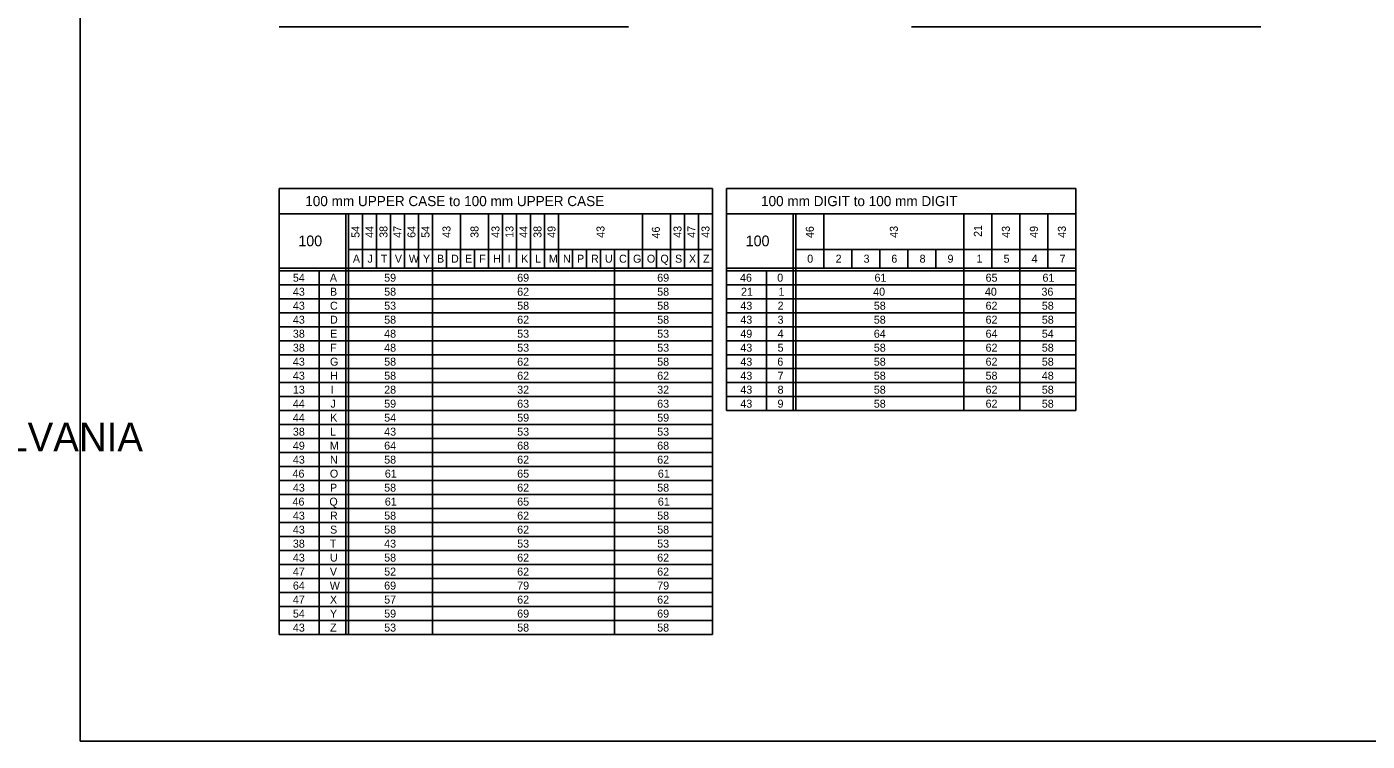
# Model space of a CAD drawing. Extents: x 637580 to 641849, y 297270 to 299646.
# Drawn here: x 638441 to 638944, y 297879 to 298147 of the extents above; entities that cross this region are included whole.
import ezdxf

# ---------------------------------------------------------------- set-up
doc = ezdxf.new("R2010")
doc.units = 0
doc.layers.add('1', color=7, linetype='Continuous')
doc.layers.add('2', color=7, linetype='Continuous')

msp = doc.modelspace()

# ---------------------------------------------------------------- linework, layer by layer
at = {"layer": '1'}
for p, q in [((638461.31, 298442.63), (638461.31, 297878.63)), ((639247.31, 297878.63), (638461.31, 297878.63)), ((638461.31, 297878.63), (639047.31, 297878.63))]:
    msp.add_line(p, q, dxfattribs=at)
at = {"layer": '2'}
for p, q in [((638535.94, 298146.63), (638666.94, 298146.63)), ((638773.06, 298146.63), (638904.06, 298146.63)), ((638698.44, 298086), (638535.94, 298086)), ((638535.94, 298086), (638535.94, 297918.63)), ((638698.44, 298086), (638698.44, 297918.63)), ((638834.69, 298086), (638703.69, 298086)), ((638703.69, 298086), (638703.69, 298002.63)), ((638834.69, 298002.63), (638834.69, 298086)), ((638535.94, 298076.5), (638698.44, 298076.5)), ((638560.94, 298076.5), (638560.94, 297918.63)), ((638561.94, 298076.5), (638561.94, 297918.63)), ((638567.19, 298076.5), (638567.19, 298056.13)), ((638572.44, 298076.5), (638572.44, 298056.13)), ((638577.69, 298076.5), (638577.69, 298056.13)), ((638582.94, 298076.5), (638582.94, 298056.13)), ((638588.19, 298076.5), (638588.19, 298056.13)), ((638593.44, 298076.5), (638593.44, 297918.63)), ((638603.94, 298076.5), (638603.94, 298056.13)), ((638614.44, 298076.5), (638614.44, 298056.13)), ((638619.69, 298076.5), (638619.69, 298056.13)), ((638624.94, 298076.5), (638624.94, 298056.13)), ((638630.19, 298076.5), (638630.19, 298056.13)), ((638635.44, 298076.5), (638635.44, 298056.13)), ((638640.69, 298076.5), (638640.69, 298056.13)), ((638672.19, 298076.5), (638672.19, 298056.13)), ((638682.69, 298076.5), (638682.69, 298056.13)), ((638687.94, 298076.5), (638687.94, 298056.13)), ((638693.19, 298076.5), (638693.19, 298056.13)), ((638703.69, 298076.5), (638834.69, 298076.5)), ((638728.69, 298076.5), (638728.69, 298002.63)), ((638729.69, 298076.5), (638729.69, 298002.63)), ((638740.19, 298076.5), (638740.19, 298056.13)), ((638792.69, 298076.5), (638792.69, 298002.63)), ((638803.19, 298076.5), (638803.19, 298056.13)), ((638813.69, 298076.5), (638813.69, 298002.63)), ((638824.19, 298076.5), (638824.19, 298056.13)), ((638561.94, 298063.13), (638698.44, 298063.13)), ((638598.69, 298063.13), (638598.69, 298056.13)), ((638609.19, 298063.13), (638609.19, 298056.13)), ((638645.94, 298063.13), (638645.94, 298056.13)), ((638651.19, 298063.13), (638651.19, 298056.13)), ((638656.44, 298063.13), (638656.44, 298056.13)), ((638656.44, 298063.13), (638656.44, 298056.13)), ((638661.69, 298063.13), (638661.69, 297918.63)), ((638666.94, 298063.13), (638666.94, 298056.13)), ((638677.44, 298063.13), (638677.44, 298056.13)), ((638729.69, 298063.13), (638834.69, 298063.13)), ((638750.69, 298063.13), (638750.69, 298056.13)), ((638761.19, 298063.13), (638761.19, 298056.13)), ((638771.69, 298063.13), (638771.69, 298056.13)), ((638782.19, 298063.13), (638782.19, 298056.13)), ((638698.44, 298056.13), (638535.94, 298056.13)), ((638698.44, 298055.13), (638535.94, 298055.13)), ((638550.94, 298055.13), (638550.94, 297918.63)), ((638834.69, 298056.13), (638703.69, 298056.13)), ((638834.69, 298055.13), (638703.69, 298055.13)), ((638718.69, 298055.13), (638718.69, 298002.63)), ((638698.44, 298049.88), (638535.94, 298049.88)), ((638834.69, 298049.88), (638703.69, 298049.88)), ((638698.44, 298044.63), (638535.94, 298044.63)), ((638834.69, 298044.63), (638703.69, 298044.63)), ((638698.44, 298039.38), (638535.94, 298039.38)), ((638834.69, 298039.38), (638703.69, 298039.38)), ((638698.44, 298034.13), (638535.94, 298034.13)), ((638834.69, 298034.13), (638703.69, 298034.13)), ((638698.44, 298028.88), (638535.94, 298028.88)), ((638834.69, 298028.88), (638703.69, 298028.88)), ((638698.44, 298023.63), (638535.94, 298023.63)), ((638834.69, 298023.63), (638703.69, 298023.63)), ((638698.44, 298018.38), (638535.94, 298018.38)), ((638834.69, 298018.38), (638703.69, 298018.38)), ((638698.44, 298013.13), (638535.94, 298013.13)), ((638834.69, 298013.13), (638703.69, 298013.13)), ((638698.44, 298007.88), (638535.94, 298007.88)), ((638834.69, 298007.88), (638703.69, 298007.88)), ((638698.44, 298002.63), (638535.94, 298002.63)), ((638703.69, 298002.63), (638834.69, 298002.63)), ((638698.44, 297997.38), (638535.94, 297997.38)), ((638698.44, 297992.13), (638535.94, 297992.13)), ((638698.44, 297986.88), (638535.94, 297986.88)), ((638698.44, 297981.63), (638535.94, 297981.63)), ((638698.44, 297976.38), (638535.94, 297976.38)), ((638698.44, 297971.13), (638535.94, 297971.13)), ((638698.44, 297965.88), (638535.94, 297965.88)), ((638698.44, 297960.63), (638535.94, 297960.63)), ((638698.44, 297955.38), (638535.94, 297955.38)), ((638698.44, 297950.13), (638535.94, 297950.13)), ((638698.44, 297944.88), (638535.94, 297944.88)), ((638698.44, 297939.63), (638535.94, 297939.63)), ((638698.44, 297934.38), (638535.94, 297934.38)), ((638698.44, 297929.13), (638535.94, 297929.13)), ((638698.44, 297923.88), (638535.94, 297923.88)), ((638535.94, 297918.63), (638535.94, 297918.63)), ((638535.94, 297918.63), (638698.44, 297918.63))]:
    msp.add_line(p, q, dxfattribs=at)

# ---------------------------------------------------------------- texts
at = {"layer": '1'}
msp.add_text('COMMONWEALTH OF PENNSYLVANIA', height=10.7828, dxfattribs=at).set_placement((638218.9, 297987.36))
at = {"layer": '2'}
for s, height, p in [('100 mm UPPER CASE to 100 mm UPPER CASE', 3.8, (638545.72, 298079.35)), ('100 mm DIGIT to 100 mm DIGIT', 3.8, (638716.63, 298079.35)), ('100', 4, (638543.13, 298064.31)), ('100', 4, (638710.88, 298064.31)), ('A', 3, (638563.58, 298058.13)), ('J', 3, (638569.07, 298058.13)), ('T', 3, (638574.07, 298058.13)), ('V', 3, (638579.33, 298058.13)), ('W', 3, (638584.56, 298058.13)), ('Y', 3, (638589.87, 298058.13)), ('B', 3, (638595.13, 298058.13)), ('D', 3, (638600.38, 298058.13)), ('E', 3, (638605.64, 298058.13)), ('F', 3, (638610.95, 298058.13)), ('H', 3, (638616.21, 298058.13)), ('I', 3, (638621.63, 298058.13)), ('K', 3, (638626.71, 298058.13)), ('L', 3, (638631.96, 298058.13)), ('M', 3, (638637.06, 298058.13)), ('N', 3, (638642.38, 298058.13)), ('P', 3, (638647.63, 298058.13)), ('R', 3, (638652.88, 298058.13)), ('U', 3, (638658.12, 298058.13)), ('C', 3, (638663.38, 298058.13)), ('G', 3, (638668.63, 298058.13)), ('O', 3, (638673.83, 298058.13)), ('Q', 3, (638678.9, 298058.13)), ('S', 3, (638684.39, 298058.13)), ('X', 3, (638689.62, 298058.13)), ('Z', 3, (638694.88, 298058.13)), ('0', 3, (638733.96, 298058.13)), ('2', 3, (638744.59, 298058.13)), ('3', 3, (638755.09, 298058.13)), ('6', 3, (638765.5, 298058.13)), ('8', 3, (638776.09, 298058.13)), ('9', 3, (638786.57, 298058.13)), ('1', 3, (638797.43, 298058.13)), ('5', 3, (638807.59, 298058.13)), ('4', 3, (638818.09, 298058.13)), ('7', 3, (638828.59, 298058.13)), ('54', 3, (638541.09, 298051)), ('A', 3, (638554.96, 298051)), ('59', 3, (638575.32, 298051)), ('69', 3, (638625.2, 298051)), ('69', 3, (638677.7, 298051)), ('46', 3, (638708.75, 298051)), ('0', 3, (638722.71, 298051)), ('61', 3, (638759.18, 298051)), ('65', 3, (638800.84, 298051)), ('61', 3, (638822.18, 298051)), ('43', 3, (638541.09, 298045.75)), ('B', 3, (638555, 298045.75)), ('58', 3, (638575.32, 298045.75)), ('62', 3, (638625.2, 298045.75)), ('58', 3, (638677.7, 298045.75)), ('21', 3, (638709.13, 298045.75)), ('1', 3, (638723.18, 298045.75)), ('40', 3, (638758.68, 298045.75)), ('40', 3, (638800.59, 298045.75)), ('36', 3, (638821.8, 298045.75)), ('43', 3, (638541.09, 298040.5)), ('C', 3, (638555, 298040.5)), ('53', 3, (638575.32, 298040.5)), ('58', 3, (638625.2, 298040.5)), ('58', 3, (638677.7, 298040.5)), ('43', 3, (638708.88, 298040.5)), ('2', 3, (638722.84, 298040.5)), ('58', 3, (638758.93, 298040.5)), ('62', 3, (638800.84, 298040.5)), ('58', 3, (638821.93, 298040.5)), ('43', 3, (638541.09, 298035.25)), ('D', 3, (638555, 298035.25)), ('58', 3, (638575.32, 298035.25)), ('62', 3, (638625.2, 298035.25)), ('58', 3, (638677.7, 298035.25)), ('43', 3, (638708.88, 298035.25)), ('3', 3, (638722.84, 298035.25)), ('58', 3, (638758.93, 298035.25)), ('62', 3, (638800.84, 298035.25)), ('58', 3, (638821.93, 298035.25)), ('38', 3, (638541.09, 298030)), ('E', 3, (638555.02, 298030)), ('48', 3, (638575.32, 298030)), ('53', 3, (638625.2, 298030)), ('53', 3, (638677.7, 298030)), ('49', 3, (638708.88, 298030)), ('4', 3, (638722.84, 298030)), ('64', 3, (638758.93, 298030)), ('64', 3, (638800.84, 298030)), ('54', 3, (638821.93, 298030)), ('38', 3, (638541.09, 298024.75)), ('F', 3, (638555.07, 298024.75)), ('48', 3, (638575.32, 298024.75)), ('53', 3, (638625.2, 298024.75)), ('53', 3, (638677.7, 298024.75)), ('43', 3, (638708.88, 298024.75)), ('5', 3, (638722.84, 298024.75)), ('58', 3, (638758.93, 298024.75)), ('62', 3, (638800.84, 298024.75)), ('58', 3, (638821.93, 298024.75)), ('43', 3, (638541.09, 298019.5)), ('G', 3, (638555, 298019.5)), ('58', 3, (638575.32, 298019.5)), ('62', 3, (638625.2, 298019.5)), ('58', 3, (638677.7, 298019.5)), ('43', 3, (638708.88, 298019.5)), ('6', 3, (638722.75, 298019.5)), ('58', 3, (638758.93, 298019.5)), ('62', 3, (638800.84, 298019.5)), ('58', 3, (638821.93, 298019.5)), ('43', 3, (638541.09, 298014.25)), ('H', 3, (638555.09, 298014.25)), ('58', 3, (638575.32, 298014.25)), ('62', 3, (638625.2, 298014.25)), ('62', 3, (638677.7, 298014.25)), ('43', 3, (638708.88, 298014.25)), ('7', 3, (638722.84, 298014.25)), ('58', 3, (638758.93, 298014.25)), ('58', 3, (638800.84, 298014.25)), ('48', 3, (638821.93, 298014.25)), ('13', 3, (638541.09, 298009)), ('I', 3, (638555.25, 298009)), ('28', 3, (638575.32, 298009)), ('32', 3, (638625.2, 298009)), ('32', 3, (638677.7, 298009)), ('43', 3, (638708.88, 298009)), ('8', 3, (638722.84, 298009)), ('58', 3, (638758.93, 298009)), ('62', 3, (638800.84, 298009)), ('58', 3, (638821.93, 298009)), ('44', 3, (638541.09, 298003.75)), ('J', 3, (638555.19, 298003.75)), ('59', 3, (638575.32, 298003.75)), ('63', 3, (638625.2, 298003.75)), ('63', 3, (638677.7, 298003.75)), ('43', 3, (638708.88, 298003.75)), ('9', 3, (638722.82, 298003.75)), ('58', 3, (638758.93, 298003.75)), ('62', 3, (638800.84, 298003.75)), ('58', 3, (638821.93, 298003.75)), ('44', 3, (638541.09, 297998.5)), ('K', 3, (638555.09, 297998.5)), ('54', 3, (638575.32, 297998.5)), ('59', 3, (638625.2, 297998.5)), ('59', 3, (638677.7, 297998.5)), ('38', 3, (638541.09, 297993.25)), ('L', 3, (638555.09, 297993.25)), ('43', 3, (638575.32, 297993.25)), ('53', 3, (638625.2, 297993.25)), ('53', 3, (638677.7, 297993.25)), ('49', 3, (638541.09, 297988)), ('M', 3, (638554.93, 297988)), ('64', 3, (638575.32, 297988)), ('68', 3, (638625.2, 297988)), ('68', 3, (638677.7, 297988)), ('43', 3, (638541.09, 297982.75)), ('N', 3, (638555, 297982.75)), ('58', 3, (638575.32, 297982.75)), ('62', 3, (638625.2, 297982.75)), ('62', 3, (638677.7, 297982.75)), ('46', 3, (638540.96, 297977.5)), ('O', 3, (638554.96, 297977.5)), ('61', 3, (638575.57, 297977.5)), ('65', 3, (638625.2, 297977.5)), ('61', 3, (638677.95, 297977.5)), ('43', 3, (638541.09, 297972.25)), ('P', 3, (638555, 297972.25)), ('58', 3, (638575.32, 297972.25)), ('62', 3, (638625.2, 297972.25)), ('58', 3, (638677.7, 297972.25)), ('46', 3, (638540.96, 297967)), ('Q', 3, (638554.78, 297967)), ('61', 3, (638575.57, 297967)), ('65', 3, (638625.2, 297967)), ('61', 3, (638677.95, 297967)), ('43', 3, (638541.09, 297961.75)), ('R', 3, (638555, 297961.75)), ('58', 3, (638575.32, 297961.75)), ('62', 3, (638625.2, 297961.75)), ('58', 3, (638677.7, 297961.75)), ('43', 3, (638541.09, 297956.5)), ('S', 3, (638555.02, 297956.5)), ('58', 3, (638575.32, 297956.5)), ('62', 3, (638625.2, 297956.5)), ('58', 3, (638677.7, 297956.5)), ('38', 3, (638541.09, 297951.25)), ('T', 3, (638554.94, 297951.25)), ('43', 3, (638575.32, 297951.25)), ('53', 3, (638625.2, 297951.25)), ('53', 3, (638677.7, 297951.25)), ('43', 3, (638541.09, 297946)), ('U', 3, (638554.99, 297946)), ('58', 3, (638575.32, 297946)), ('62', 3, (638625.2, 297946)), ('62', 3, (638677.7, 297946)), ('47', 3, (638541.09, 297940.75)), ('V', 3, (638554.96, 297940.75)), ('52', 3, (638575.32, 297940.75)), ('62', 3, (638625.2, 297940.75)), ('62', 3, (638677.7, 297940.75)), ('64', 3, (638541.09, 297935.5)), ('W', 3, (638554.93, 297935.5)), ('69', 3, (638575.32, 297935.5)), ('79', 3, (638625.2, 297935.5)), ('79', 3, (638677.7, 297935.5)), ('47', 3, (638541.09, 297930.25)), ('X', 3, (638554.99, 297930.25)), ('57', 3, (638575.32, 297930.25)), ('62', 3, (638625.2, 297930.25)), ('62', 3, (638677.7, 297930.25)), ('54', 3, (638541.09, 297925)), ('Y', 3, (638554.99, 297925)), ('59', 3, (638575.32, 297925)), ('69', 3, (638625.2, 297925)), ('69', 3, (638677.7, 297925)), ('43', 3, (638541.09, 297919.75)), ('Z', 3, (638555, 297919.75)), ('53', 3, (638575.32, 297919.75)), ('58', 3, (638625.2, 297919.75)), ('58', 3, (638677.7, 297919.75))]:
    msp.add_text(s, height=height, dxfattribs=at).set_placement(p)
for s, p in [('54', (638566.06, 298067.46)), ('44', (638571.31, 298067.46)), ('38', (638576.56, 298067.46)), ('47', (638581.81, 298067.46)), ('64', (638587.06, 298067.46)), ('54', (638592.31, 298067.46)), ('43', (638600.19, 298067.46)), ('38', (638610.69, 298067.46)), ('43', (638618.56, 298067.46)), ('13', (638623.81, 298067.46)), ('44', (638629.06, 298067.46)), ('38', (638634.31, 298067.46)), ('49', (638639.56, 298067.45)), ('43', (638657.94, 298067.46)), ('46', (638678.69, 298067.21)), ('43', (638686.81, 298067.46)), ('47', (638692.06, 298067.46)), ('43', (638697.31, 298067.46)), ('46', (638736.44, 298067.38)), ('43', (638767.94, 298067.46)), ('21', (638799.44, 298067.81)), ('43', (638809.94, 298067.46)), ('49', (638820.44, 298067.45)), ('43', (638830.94, 298067.46))]:
    msp.add_text(s, height=3, rotation=90, dxfattribs=at).set_placement(p)

doc.saveas('drawing.dxf')
